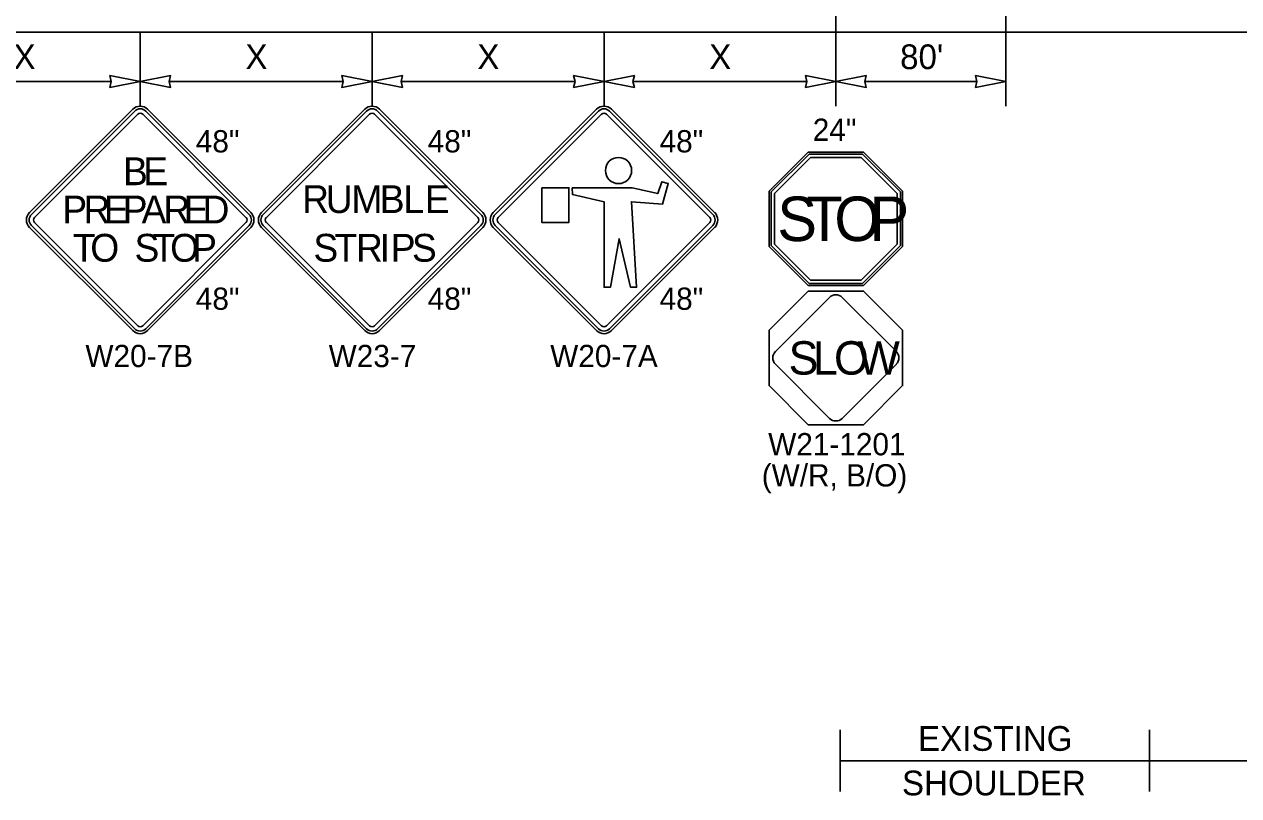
# Model space of a CAD drawing. Extents: x 99999.1 to 100095.7, y 99995 to 100010.7.
# Drawn here: x 100041.652 to 100045.58, y 100003.262 to 100005.757 of the extents above; entities that cross this region are included whole.
import ezdxf

# ---------------------------------------------------------------- set-up
doc = ezdxf.new("R2010")
doc.units = 0
for name, color, linetype in [('RD_ED_ShoulderPavedEdge', 7, 'Continuous'), ('TR_SN_ConstructionSigns', 7, 'Continuous'), ('TR_WZ_WorkZoneDetails', 7, 'Continuous'), ('TR_WZ_WorkZoneTextCurrent', 7, 'Continuous')]:
    doc.layers.add(name, color=color, linetype=linetype)

msp = doc.modelspace()

# ---------------------------------------------------------------- linework, layer by layer
at = {"layer": 'RD_ED_ShoulderPavedEdge'}
msp.add_line((100040.1076, 100005.7323), (100055.6424, 100005.7323), dxfattribs=at)
at = {"layer": 'TR_SN_ConstructionSigns'}
for p, q in [((100042.0028, 100005.4824), (100041.6687, 100005.1483)), ((100042.0088, 100005.4765), (100041.6746, 100005.1424)), ((100041.6846, 100005.1324), (100042.0187, 100005.4665)), ((100042.0346, 100005.4665), (100042.3687, 100005.1324)), ((100042.3787, 100005.1424), (100042.0445, 100005.4765)), ((100042.3846, 100005.1483), (100042.0505, 100005.4824)), ((100042.7528, 100005.4824), (100042.4187, 100005.1483)), ((100042.7588, 100005.4765), (100042.4246, 100005.1424)), ((100042.4346, 100005.1324), (100042.7687, 100005.4665)), ((100042.7846, 100005.4665), (100043.1187, 100005.1324)), ((100043.1287, 100005.1424), (100042.7945, 100005.4765)), ((100043.1346, 100005.1483), (100042.8005, 100005.4824)), ((100043.5028, 100005.4824), (100043.1687, 100005.1483)), ((100043.5088, 100005.4765), (100043.1746, 100005.1424)), ((100043.1846, 100005.1324), (100043.5187, 100005.4665)), ((100043.5346, 100005.4665), (100043.8687, 100005.1324)), ((100043.8787, 100005.1424), (100043.5445, 100005.4765)), ((100043.8846, 100005.1483), (100043.5505, 100005.4824)), ((100044.1871, 100005.3443), (100044.0606, 100005.2178)), ((100044.366, 100005.3443), (100044.1871, 100005.3443)), ((100044.4926, 100005.2178), (100044.366, 100005.3443)), ((100044.1899, 100005.3376), (100044.0673, 100005.215)), ((100044.0786, 100005.2104), (100044.1945, 100005.3263)), ((100044.3632, 100005.3376), (100044.1899, 100005.3376)), ((100044.1945, 100005.3263), (100044.3586, 100005.3263)), ((100044.3586, 100005.3263), (100044.4746, 100005.2104)), ((100044.4858, 100005.215), (100044.3632, 100005.3376)), ((100044.0606, 100005.2178), (100044.0606, 100005.0389)), ((100044.0673, 100005.215), (100044.0673, 100005.0417)), ((100044.0786, 100005.0463), (100044.0786, 100005.2104)), ((100044.4746, 100005.2104), (100044.4746, 100005.0463)), ((100044.4858, 100005.0417), (100044.4858, 100005.215)), ((100044.4926, 100005.0389), (100044.4926, 100005.2178)), ((100041.6746, 100005.1066), (100042.0088, 100004.7725)), ((100042.0187, 100004.7824), (100041.6846, 100005.1165)), ((100042.3687, 100005.1165), (100042.0346, 100004.7824)), ((100042.0445, 100004.7725), (100042.3787, 100005.1066)), ((100042.4246, 100005.1066), (100042.7588, 100004.7725)), ((100042.7687, 100004.7824), (100042.4346, 100005.1165)), ((100043.1187, 100005.1165), (100042.7846, 100004.7824)), ((100042.7945, 100004.7725), (100043.1287, 100005.1066)), ((100043.1746, 100005.1066), (100043.5088, 100004.7725)), ((100043.5187, 100004.7824), (100043.1846, 100005.1165)), ((100043.8687, 100005.1165), (100043.5346, 100004.7824)), ((100043.5445, 100004.7725), (100043.8787, 100005.1066)), ((100041.6687, 100005.1006), (100042.0028, 100004.7665)), ((100042.0505, 100004.7665), (100042.3846, 100005.1006)), ((100042.4187, 100005.1006), (100042.7528, 100004.7665)), ((100042.8005, 100004.7665), (100043.1346, 100005.1006)), ((100043.1687, 100005.1006), (100043.5028, 100004.7665)), ((100043.5505, 100004.7665), (100043.8846, 100005.1006)), ((100044.0606, 100005.0389), (100044.1871, 100004.9123)), ((100044.0673, 100005.0417), (100044.1899, 100004.9191)), ((100044.1945, 100004.9303), (100044.0786, 100005.0463)), ((100044.4746, 100005.0463), (100044.3586, 100004.9303)), ((100044.3632, 100004.9191), (100044.4858, 100005.0417)), ((100044.366, 100004.9123), (100044.4926, 100005.0389)), ((100044.1871, 100004.9123), (100044.366, 100004.9123)), ((100044.1899, 100004.9191), (100044.3632, 100004.9191)), ((100044.3586, 100004.9303), (100044.1945, 100004.9303)), ((100044.2562, 100004.874), (100044.0809, 100004.6987)), ((100044.4722, 100004.6987), (100044.2969, 100004.874)), ((100044.0809, 100004.658), (100044.2562, 100004.4827)), ((100044.2969, 100004.4827), (100044.4722, 100004.658))]:
    msp.add_line(p, q, dxfattribs=at)
for points in [[(100043.3254, 100005.2286), (100043.3254, 100005.1164), (100043.413, 100005.1164), (100043.413, 100005.2286)], [(100043.4233, 100005.2289), (100043.4246, 100005.2072), (100043.5272, 100005.1833), (100043.5272, 100004.907), (100043.5472, 100004.907), (100043.5753, 100005.064), (100043.6128, 100004.907), (100043.6319, 100004.907), (100043.6152, 100005.1832), (100043.7155, 100005.1751), (100043.7344, 100005.2421), (100043.7137, 100005.248), (100043.7005, 100005.2097), (100043.6176, 100005.2289)], [(100044.4926, 100004.7678), (100044.4926, 100004.5889), (100044.366, 100004.4623), (100044.1871, 100004.4623), (100044.0606, 100004.5889), (100044.0606, 100004.7678), (100044.1871, 100004.8943), (100044.366, 100004.8943)]]:
    msp.add_lwpolyline(points, close=True, dxfattribs=at)
msp.add_circle((100043.5736, 100005.2844), 0.0424, dxfattribs=at)
for centre, radius, start, end in [((100042.0267, 100005.4586), 0.0338, 45, 135), ((100042.0267, 100005.4586), 0.0253, 45, 135), ((100042.0267, 100005.4586), 0.0113, 45, 135), ((100042.7767, 100005.4586), 0.0338, 45, 135), ((100042.7767, 100005.4586), 0.0253, 45, 135), ((100042.7767, 100005.4586), 0.0113, 45, 135), ((100043.5267, 100005.4586), 0.0338, 45, 135), ((100043.5267, 100005.4586), 0.0253, 45, 135), ((100043.5267, 100005.4586), 0.0113, 45, 135), ((100041.6925, 100005.1245), 0.0338, 135, 225), ((100042.3608, 100005.1245), 0.0338, 315, 45), ((100042.4425, 100005.1245), 0.0338, 135, 225), ((100043.1108, 100005.1245), 0.0338, 315, 45), ((100043.1925, 100005.1245), 0.0338, 135, 225), ((100043.8608, 100005.1245), 0.0338, 315, 45), ((100041.6925, 100005.1245), 0.0253, 135, 225), ((100041.6925, 100005.1245), 0.0113, 135, 225), ((100042.3608, 100005.1245), 0.0113, 315, 45), ((100042.3608, 100005.1245), 0.0253, 315, 45), ((100042.4425, 100005.1245), 0.0253, 135, 225), ((100042.4425, 100005.1245), 0.0113, 135, 225), ((100043.1108, 100005.1245), 0.0113, 315, 45), ((100043.1108, 100005.1245), 0.0253, 315, 45), ((100043.1925, 100005.1245), 0.0253, 135, 225), ((100043.1925, 100005.1245), 0.0113, 135, 225), ((100043.8608, 100005.1245), 0.0113, 315, 45), ((100043.8608, 100005.1245), 0.0253, 315, 45), ((100044.2766, 100004.8536), 0.0288, 45, 135), ((100042.0267, 100004.7904), 0.0338, 225, 315), ((100042.0267, 100004.7904), 0.0253, 225, 315), ((100042.0267, 100004.7904), 0.0113, 225, 315), ((100042.7767, 100004.7904), 0.0338, 225, 315), ((100042.7767, 100004.7904), 0.0253, 225, 315), ((100042.7767, 100004.7904), 0.0113, 225, 315), ((100043.5267, 100004.7904), 0.0338, 225, 315), ((100043.5267, 100004.7904), 0.0253, 225, 315), ((100043.5267, 100004.7904), 0.0113, 225, 315), ((100044.1013, 100004.6783), 0.0288, 135, 225), ((100044.4518, 100004.6783), 0.0288, 315, 45), ((100044.2766, 100004.5031), 0.0288, 225, 315)]:
    msp.add_arc(centre, radius, start, end, dxfattribs=at)
at = {"layer": 'TR_WZ_WorkZoneDetails'}
for p, q in [((100044.2767, 100008.9491), (100044.2767, 100005.4923)), ((100044.8267, 100005.4923), (100044.8267, 100007.7323)), ((100042.0267, 100005.7323), (100042.0267, 100005.4923)), ((100042.7767, 100005.7323), (100042.7767, 100005.4923)), ((100043.5267, 100005.7323), (100043.5267, 100005.4923)), ((100041.9329, 100005.5723), (100041.3704, 100005.5723)), ((100042.6829, 100005.5723), (100042.1204, 100005.5723)), ((100043.4329, 100005.5723), (100042.8704, 100005.5723)), ((100044.1829, 100005.5723), (100043.6204, 100005.5723)), ((100044.7329, 100005.5723), (100044.3704, 100005.5723)), ((100044.2907, 100003.2755), (100044.2907, 100003.4755)), ((100045.2907, 100003.2755), (100045.2907, 100003.4755)), ((100044.2907, 100003.3755), (100045.2907, 100003.3755)), ((100045.2907, 100003.3755), (100046.4907, 100003.3755))]:
    msp.add_line(p, q, dxfattribs=at)
for points in [[(100042.0267, 100005.5723), (100041.9284, 100005.5916), (100041.9329, 100005.5723), (100041.9284, 100005.5531)], [(100042.0267, 100005.5723), (100042.1249, 100005.5916), (100042.1204, 100005.5723), (100042.1249, 100005.5531)], [(100042.7767, 100005.5723), (100042.6784, 100005.5916), (100042.6829, 100005.5723), (100042.6784, 100005.5531)], [(100042.7767, 100005.5723), (100042.8749, 100005.5916), (100042.8704, 100005.5723), (100042.8749, 100005.5531)], [(100043.5267, 100005.5723), (100043.4284, 100005.5916), (100043.4329, 100005.5723), (100043.4284, 100005.5531)], [(100043.5267, 100005.5723), (100043.6249, 100005.5916), (100043.6204, 100005.5723), (100043.6249, 100005.5531)], [(100044.2767, 100005.5723), (100044.1784, 100005.5916), (100044.1829, 100005.5723), (100044.1784, 100005.5531)], [(100044.2767, 100005.5723), (100044.3749, 100005.5916), (100044.3704, 100005.5723), (100044.3749, 100005.5531)], [(100044.8267, 100005.5723), (100044.7284, 100005.5916), (100044.7329, 100005.5723), (100044.7284, 100005.5531)]]:
    msp.add_lwpolyline(points, close=True, dxfattribs=at)

# ---------------------------------------------------------------- texts
at = {"layer": 'TR_SN_ConstructionSigns'}
for s, height, p in [('24"', 0.072, (100044.2019, 100005.3803)), ('B', 0.09, (100041.9709, 100005.237)), ('E', 0.09, (100042.0366, 100005.237)), ('R', 0.09, (100042.5503, 100005.147)), ('U', 0.09, (100042.6268, 100005.147)), ('M', 0.09, (100042.7096, 100005.147)), ('B', 0.09, (100042.8014, 100005.147)), ('L', 0.09, (100042.8779, 100005.147)), ('E', 0.09, (100042.9472, 100005.147)), ('P', 0.09, (100041.7747, 100005.1132)), ('R', 0.09, (100041.8431, 100005.1132)), ('E', 0.09, (100041.9088, 100005.1132)), ('P', 0.09, (100041.97, 100005.1132)), ('A', 0.09, (100042.0312, 100005.1132)), ('R', 0.09, (100042.1014, 100005.1132)), ('E', 0.09, (100042.1671, 100005.1132)), ('D', 0.09, (100042.2283, 100005.1132)), ('S', 0.144, (100044.0872, 100005.0563)), ('T', 0.144, (100044.1808, 100005.0563)), ('O', 0.144, (100044.2715, 100005.0563)), ('P', 0.144, (100044.3853, 100005.0563)), ('T', 0.09, (100041.8084, 100004.9895)), ('O', 0.09, (100041.8651, 100004.9895)), ('S', 0.09, (100042.0082, 100004.9895)), ('T', 0.09, (100042.0667, 100004.9895)), ('O', 0.09, (100042.1234, 100004.9895)), ('P', 0.09, (100042.1945, 100004.9895)), ('S', 0.09, (100042.5868, 100004.9895)), ('T', 0.09, (100042.6552, 100004.9895)), ('R', 0.09, (100042.7245, 100004.9895)), ('I', 0.09, (100042.801, 100004.9895)), ('P', 0.09, (100042.837, 100004.9895)), ('S', 0.09, (100042.9054, 100004.9895)), ('S', 0.108, (100044.1238, 100004.6243)), ('L', 0.108, (100044.2026, 100004.6243)), ('O', 0.108, (100044.2706, 100004.6243)), ('W', 0.108, (100044.3473, 100004.6243))]:
    msp.add_text(s, height=height, dxfattribs=at).set_placement(p)
for s, p in [('48"', (100042.2064, 100005.343)), ('48"', (100042.9564, 100005.343)), ('48"', (100043.7064, 100005.343)), ('48"', (100042.2064, 100004.8339)), ('48"', (100042.9564, 100004.8339)), ('48"', (100043.7064, 100004.8339)), ('W20-7B', (100041.8493, 100004.6486)), ('W23-7', (100042.6361, 100004.6486)), ('W20-7A', (100043.3527, 100004.6486)), ('W21-1201', (100044.0578, 100004.3633)), ('(W/R, B/O)', (100044.0369, 100004.2625))]:
    msp.add_text(s, height=0.072, rotation=360, dxfattribs=at).set_placement(p)
at = {"layer": 'TR_WZ_WorkZoneDetails'}
for s, p in [('EXISTING', (100044.5424, 100003.4075)), ('SHOULDER', (100044.4905, 100003.2635))]:
    msp.add_text(s, height=0.08, rotation=360, dxfattribs=at).set_placement(p)
at = {"layer": 'TR_WZ_WorkZoneTextCurrent'}
for s, p in [("80'", (100044.4844, 100005.6123)), ('X', (100041.6169, 100005.6123)), ('X', (100042.3669, 100005.6123)), ('X', (100043.1169, 100005.6123)), ('X', (100043.8669, 100005.6123))]:
    msp.add_text(s, height=0.08, rotation=360, dxfattribs=at).set_placement(p)

doc.saveas('drawing.dxf')
